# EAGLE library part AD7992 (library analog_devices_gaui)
16-Bit DAC with Serial Data Interface
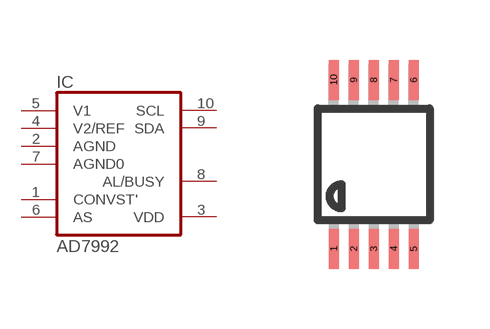
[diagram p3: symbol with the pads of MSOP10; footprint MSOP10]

Designator prefix IC

## AD7992  [MSOP10]
1  CONVST'  in
2  AGND  pwr
3  VDD  pwr
4  V2/REF  in
5  V1  in
6  AS  in
7  AGND0  pwr
8  AL/BUSY  out
9  SDA  out
10  SCL  out

## Footprint MSOP10 (pad centres in mm)
10-Lead Mini Small Outline Package [MSOP] (RM-10) Source: http://www.analog.com/UploadedFiles/Data_Sheets/35641221898805SSM2167_b.pdf COMPLIANT TO JEDEC STANDARDS MO-187BA
smd 0.25 x 1: 1 -1,-2.113; 2 -0.5,-2.113; 3 0,-2.113; 4 0.5,-2.113; 5 1,-2.113; 6 1,2.113; 7 0.5,2.113; 8 0,2.113; 9 -0.5,2.113; 10 -1,2.113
